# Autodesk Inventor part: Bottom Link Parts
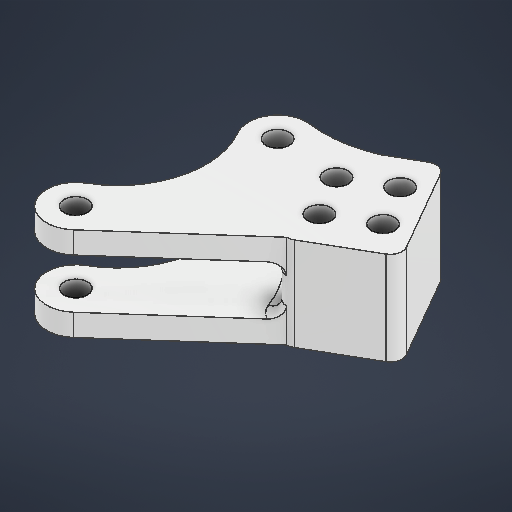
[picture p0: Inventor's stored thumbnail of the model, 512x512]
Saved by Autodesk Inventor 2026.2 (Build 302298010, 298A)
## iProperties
Created: 2026-05
Part Number: Bottom Link Parts
Material: ABS 플라스틱
Document SubType Name: Modeling
Designer: work
Density: 1.06 g/cm^3
Appearance: 매끄러움 - 흰색
Author: work
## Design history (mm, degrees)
sketch "스케치1"
  geometry: L1 (0, 0)-(-17.321, -10); L2 (-17.321, -10)-(-7.321, -27.321); L3 (-7.321, -27.321)-(56.423, -27.321); L4 (-35.507, -20.5)-(-25.507, -37.821); L5 (-25.507, -37.821)-(-11.651, -29.821); L6 (-11.651, -29.821)-(-21.651, -12.5); L7 (-21.651, -12.5)-(-35.507, -20.5); L8 (-35.507, -20.5)-(-11.651, -29.821); L9 (-25.507, -37.821)-(-21.651, -12.5); L10 (-12.321, -18.66)-(-23.579, -25.16); L11 (-29.043, -23.696)-(-25.043, -30.624); L12 (-25.043, -30.624)-(-18.115, -26.624); L13 (-18.115, -26.624)-(-22.115, -19.696); L14 (-22.115, -19.696)-(-29.043, -23.696); L15 (-29.043, -23.696)-(-18.115, -26.624); L16 (-25.043, -30.624)-(-22.115, -19.696); L17 (-3.316, 3.743)-(-21.651, -12.5); C1 r 2 at (0, 0); C2 r 2 at (-7.321, -27.321); C3 r 2 at (-22.115, -19.696); C4 r 2 at (-29.043, -23.696); C5 r 2 at (-18.115, -26.624); C6 r 2 at (-25.043, -30.624); A1 r 5 centre (0, 0) between (-3.316, 3.743) and (2.5, -4.33); A2 r 5 centre (-7.321, -27.321) between (-11.651, -29.821) and (-2.99, -24.821); A3 r 15 centre (10, -17.321) between (2.5, -4.33) and (-2.99, -24.821); A4 r 20 centre (-10.502, -52.117) between (-7.957, -32.28) and (-18.579, -33.821); 2 further points
  constraints: 34 end point, 10 centre point, 9 point on circle, 8 coincident, 8 midpoint, 5 parallel, 4 perpendicular, 4 tangent, 1 horizontal
  dimensions: "d0" = 4 diameter of C1; "d1" = 20 distance of L1.start L1.end; "d2" = 4 diameter of C2; "d3" = 20 distance of L1.end L2.end; "d4" = 30 deg angle of L3 L1; "d5" = 10 diameter of A1; "d6" = 10 diameter of A2; "d7" = 20 distance of L5.end L6.end; "d8" = 6 distance between parallel lines of L5 L12; "d9" = 4 distance between parallel lines of L4 L11; "d10" = 16 distance of L6.end L4.start; "d11" = 4 diameter of C3; "d12" = 4 diameter of C4; "d13" = 4 diameter of C5; "d14" = 4 diameter of C6; "d15" = 15 radius of A3; "d16" = 20 radius of A4
extrude "돌출1" new body sketch "스케치1" distance "d17" = 16; taper "d18" = 0 deg
node "작업 평면1"
sketch "스케치2"
  geometry: L1 (25.507, -37.821)-(18.579, -33.821) reference; L2 (3.316, 3.743)-(21.651, -12.5) reference; L3 (3.316, 3.743)-(21.651, -12.5) reference; L4 (25.507, -37.821)-(18.579, -33.821) reference; L5 (35.507, -20.5)-(25.507, -37.821) reference; L6 (21.651, -12.5)-(35.507, -20.5) reference; C1 r 2 at (7.321, -27.321) reference; C2 r 2 at (25.043, -30.624) reference; C3 r 2 at (18.115, -26.624) reference; C4 r 2 at (29.043, -23.696) reference; C5 r 2 at (22.115, -19.696) reference; C6 r 2 at (0, 0) reference; C7 r 6.5 at (7.321, -27.321); A1 r 5 centre (0, 0) between (3.316, 3.743) and (-2.5, -4.33) reference; A2 r 15 centre (-10, -17.321) between (2.99, -24.821) and (-2.5, -4.33) reference; A3 r 5 centre (7.321, -27.321) between (2.99, -24.821) and (7.957, -32.28) reference; A4 r 20 centre (10.502, -52.117) between (18.579, -33.821) and (7.957, -32.28) reference; A5 r 25 centre (-2.402, -5.683) between (15.094, -23.541) and (21.651, -12.5); 7 further points
  constraints: 2 centre point, 2 point on circle, 1 coincident, 1 concentric, 5 other
  dimensions: "d19" = 13 diameter of C7; "d20" = 25 radius of A5
extrude "돌출2" cut sketch "스케치2" stored distance "d21" = 8.5; taper "d22" = 0 deg
fillet "모깎기1" dims "d23" = 2
node "솔리드1"
node "투영된 루프1"
other parameters: "sa_0" = 4
